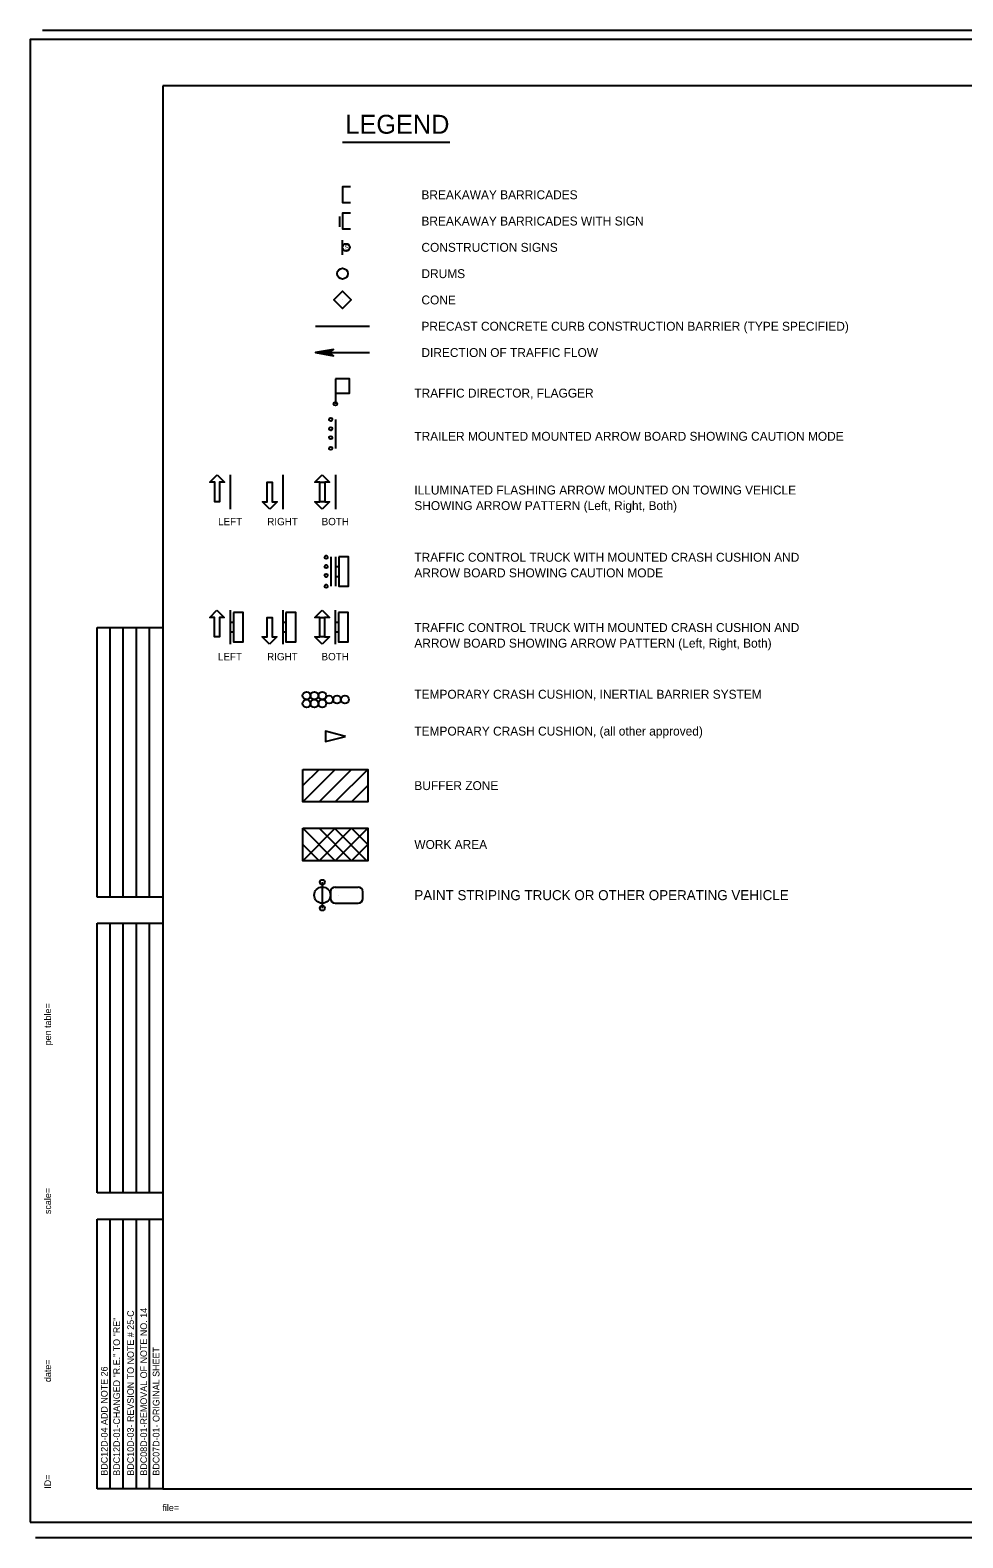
# Model space of a CAD drawing. Extents: x 499940 to 501011, y 499978 to 500655.
# Drawn here: x 499940 to 500359, y 499978 to 500655 of the extents above; entities that cross this region are included whole.
import ezdxf

# ---------------------------------------------------------------- set-up
doc = ezdxf.new("R2010")
doc.units = 0
for name, color, linetype in [('1', 7, 'Continuous'), ('24', 7, 'Continuous'), ('41', 7, 'Continuous'), ('5', 7, 'Continuous'), ('56', 7, 'Continuous'), ('60', 7, 'Continuous')]:
    doc.layers.add(name, color=color, linetype=linetype)

msp = doc.modelspace()

# ---------------------------------------------------------------- linework, layer by layer
at = {"layer": '1'}
for p, q in [((499946.02, 500655.04), (501011.03, 500655.04)), ((500000, 500630), (500000, 500000)), ((500990, 500630), (500000, 500630)), ((500080.76, 500604.79), (500128.92, 500604.79)), ((500080.76, 500533.87), (500080.76, 500533.87)), ((500068.59, 500522.06), (500092.93, 500522.06)), ((500068.59, 500510.25), (500092.93, 500510.25)), ((500077.56, 500480.24), (500077.56, 500467.1)), ((500030.32, 500455.29), (500030.32, 500439.95)), ((500053.94, 500455.29), (500053.94, 500439.95)), ((500077.56, 500455.29), (500077.56, 500442.14)), ((500077.56, 500455.29), (500077.56, 500439.95)), ((500075.51, 500418.52), (500075.51, 500405.38)), ((500077.56, 500418.52), (500077.56, 500405.38)), ((500077.56, 500414.14), (500079.02, 500414.14)), ((500077.56, 500409.76), (500079.02, 500409.76)), ((500030.26, 500394.63), (500030.26, 500379.29)), ((500053.88, 500394.63), (500053.88, 500379.29)), ((500077.5, 500394.63), (500077.5, 500379.29)), ((499970.47, 500265.75), (499970.47, 500386.81)), ((499970.47, 500386.81), (500000, 500386.81)), ((499976.38, 500265.75), (499976.38, 500386.81)), ((499982.28, 500265.75), (499982.28, 500386.81)), ((499988.19, 500265.75), (499988.19, 500386.81)), ((499994.09, 500265.75), (499994.09, 500386.81)), ((500030.26, 500389.15), (500031.72, 500389.15)), ((500053.88, 500389.15), (500055.34, 500389.15)), ((500077.5, 500389.15), (500078.96, 500389.15)), ((500030.26, 500384.77), (500031.72, 500384.77)), ((500053.88, 500384.77), (500055.34, 500384.77)), ((500077.5, 500384.77), (500078.96, 500384.77)), ((500071.66, 500272.44), (500071.66, 500260.76)), ((500000, 500265.75), (499970.47, 500265.75)), ((500075.31, 500268.06), (500075.31, 500265.14)), ((500077.5, 500270.25), (500087.72, 500270.25)), ((500078.96, 500266.6), (500078.96, 500266.6)), ((500089.91, 500265.14), (500089.91, 500268.06)), ((500077.5, 500262.95), (500087.72, 500262.95)), ((499970.47, 500132.87), (499970.47, 500253.94)), ((499970.47, 500253.94), (500000, 500253.94)), ((499976.38, 500132.87), (499976.38, 500253.94)), ((499982.28, 500132.87), (499982.28, 500253.94)), ((499988.19, 500132.87), (499988.19, 500253.94)), ((499994.09, 500132.87), (499994.09, 500253.94)), ((500000, 500132.87), (499970.47, 500132.87)), ((499970.47, 500000), (499970.47, 500121.06)), ((499970.47, 500121.06), (500000, 500121.06)), ((499976.38, 500000), (499976.38, 500121.06)), ((499982.28, 500000), (499982.28, 500121.06)), ((499988.19, 500000), (499988.19, 500121.06)), ((499994.09, 500000), (499994.09, 500121.06)), ((500000, 500000), (499970.47, 500000)), ((500000, 500000), (500990, 500000)), ((501007.77, 499977.98), (499942.76, 499977.98))]:
    msp.add_line(p, q, dxfattribs=at)
msp.add_lwpolyline([(500076.85, 500533.98), (500080.79, 500530.04), (500084.66, 500533.91), (500080.72, 500537.85)], close=True, dxfattribs=at)
msp.add_circle((500071.66, 500266.6), 3.65, dxfattribs=at)
for centre, start, end in [((500077.5, 500268.06), 90, 180), ((500077.5, 500265.14), 180, 270), ((500087.72, 500268.06), 0, 90), ((500087.72, 500265.14), 270, 0)]:
    msp.add_arc(centre, 2.19, start, end, dxfattribs=at)
at = {"layer": '24'}
msp.add_lwpolyline([(500068.59, 500510.25), (500076.68, 500508.82), (500074.75, 500510.25), (500076.64, 500511.66), (500068.59, 500510.25), (500069.12, 500510.27), (500076.46, 500508.93), (500074.6, 500510.27), (500076.31, 500511.55), (500069.41, 500510.29), (500069.68, 500510.25), (500075.96, 500509.14), (500074.56, 500510.27), (500076, 500511.37), (500069.81, 500510.25), (500070.08, 500510.29), (500075.57, 500509.3), (500074.5, 500510.25), (500075.59, 500511.24), (500070.86, 500510.29), (500071.31, 500510.29), (500075.16, 500509.51), (500074.41, 500510.23), (500075.22, 500511.04), (500071.4, 500510.25), (500071.83, 500510.23), (500074.72, 500509.73), (500074.16, 500510.29), (500074.77, 500510.85), (500072.23, 500510.25), (500072.63, 500510.21), (500074.37, 500509.88), (500074.08, 500510.27), (500074.56, 500510.7), (500072.85, 500510.25), (500073.98, 500509.98), (500073.81, 500510.29), (500074.31, 500510.6), (500073.13, 500510.29), (500073.87, 500510.11), (500073.56, 500510.35), (500073.92, 500510.5), (500073.56, 500510.27), (500073.75, 500510.23)], dxfattribs=at)
at = {"layer": '41'}
msp.add_lwpolyline([(499940.42, 499984.98), (501004.97, 499984.98), (501004.97, 500650.84), (499940.42, 500650.84)], close=True, dxfattribs=at)
at = {"layer": '5'}
msp.add_line((500077.56, 500492.05), (500077.56, 500487.26), dxfattribs=at)
msp.add_circle((500077.56, 500487.26), 0.799, dxfattribs=at)
at = {"layer": '56'}
for p, q in [((500079.35, 500571.43), (500079.35, 500566.78)), ((500080.76, 500554.21), (500080.76, 500560.78)), ((500062.9, 500308.48), (500077.5, 500323.08)), ((500062.9, 500315.78), (500070.2, 500323.08)), ((500070.2, 500308.48), (500084.8, 500323.08)), ((500077.5, 500308.48), (500092.11, 500323.08)), ((500084.8, 500308.48), (500092.11, 500315.78)), ((500062.9, 500282.06), (500077.5, 500296.66)), ((500077.5, 500282.06), (500062.9, 500296.66)), ((500070.2, 500282.06), (500084.8, 500296.66)), ((500084.8, 500282.06), (500070.2, 500296.66)), ((500091.72, 500282.06), (500077.12, 500296.66)), ((500077.5, 500282.06), (500092.11, 500296.66)), ((500092.11, 500289.36), (500084.8, 500296.66)), ((500070.2, 500282.06), (500062.9, 500289.36)), ((500084.8, 500282.06), (500092.11, 500289.36))]:
    msp.add_line(p, q, dxfattribs=at)
for points in [[(500084.26, 500584.62), (500080.76, 500584.62), (500080.76, 500581.12), (500080.76, 500577.61), (500084.26, 500577.61)], [(500084.26, 500572.81), (500080.76, 500572.81), (500080.76, 500569.31), (500080.76, 500565.8), (500084.26, 500565.8)], [(500024.41, 500455.29), (500027.7, 500452), (500025.51, 500452), (500025.51, 500443.24), (500023.32, 500443.24), (500023.32, 500452), (500021.13, 500452), (500024.41, 500455.29)], [(500071.66, 500455.29), (500074.94, 500452), (500072.75, 500452), (500072.75, 500443.24), (500070.56, 500443.24), (500070.56, 500452), (500068.37, 500452), (500071.66, 500455.29)], [(500048.03, 500439.95), (500044.75, 500443.24), (500046.94, 500443.24), (500046.94, 500452), (500049.13, 500452), (500049.13, 500443.24), (500051.32, 500443.24), (500048.03, 500439.95)], [(500071.66, 500439.95), (500068.37, 500443.24), (500070.56, 500443.24), (500070.56, 500452), (500072.75, 500452), (500072.75, 500443.24), (500074.94, 500443.24), (500071.66, 500439.95)], [(500024.35, 500394.62), (500027.64, 500391.34), (500025.45, 500391.34), (500025.45, 500382.57), (500023.26, 500382.57), (500023.26, 500391.34), (500021.07, 500391.34), (500024.35, 500394.62)], [(500071.6, 500394.62), (500074.88, 500391.34), (500072.69, 500391.34), (500072.69, 500382.57), (500070.5, 500382.57), (500070.5, 500391.34), (500068.31, 500391.34), (500071.6, 500394.62)], [(500047.98, 500379.29), (500044.69, 500382.57), (500046.88, 500382.57), (500046.88, 500391.34), (500049.07, 500391.34), (500049.07, 500382.57), (500051.26, 500382.57), (500047.98, 500379.29)], [(500071.6, 500379.29), (500068.31, 500382.57), (500070.5, 500382.57), (500070.5, 500391.34), (500072.69, 500391.34), (500072.69, 500382.57), (500074.88, 500382.57), (500071.6, 500379.29)], [(500082.03, 500337.87), (500073.04, 500340.26), (500073.04, 500335.53), (500082.03, 500337.87)], [(500062.9, 500323.08), (500092.11, 500323.08), (500092.11, 500308.48), (500062.9, 500308.48), (500062.9, 500323.08)], [(500062.9, 500296.66), (500092.11, 500296.66), (500092.11, 500282.06), (500062.9, 500282.06), (500062.9, 500296.66)]]:
    msp.add_lwpolyline(points, dxfattribs=at)
msp.add_lwpolyline([(500077.56, 500498.44), (500077.56, 500492.05), (500083.95, 500492.05), (500083.95, 500498.44)], close=True, dxfattribs=at)
for centre, radius in [((500082.4, 500557.5), 1.64), ((500080.76, 500545.69), 2.41), ((500064.58, 500356.18), 1.77), ((500064.58, 500352.63), 1.77), ((500068.12, 500356.18), 1.77), ((500068.12, 500352.63), 1.77), ((500071.66, 500356.18), 1.77), ((500071.66, 500352.63), 1.77), ((500074.73, 500354.41), 1.77), ((500078.27, 500354.41), 1.77), ((500081.81, 500354.41), 1.77)]:
    msp.add_circle(centre, radius, dxfattribs=at)
at = {"layer": '60'}
for points in [[(500080.72, 500537.85), (500076.85, 500533.98), (500080.79, 500530.04), (500084.66, 500533.91)], [(500077.56, 500498.44), (500077.56, 500492.05), (500083.95, 500492.05), (500083.95, 500498.44)], [(500024.41, 500455.29), (500027.7, 500452), (500025.51, 500452), (500025.51, 500443.24), (500023.32, 500443.24), (500023.32, 500452), (500021.13, 500452)], [(500071.66, 500455.29), (500074.94, 500452), (500072.75, 500452), (500072.75, 500443.24), (500070.56, 500443.24), (500070.56, 500452), (500068.37, 500452)], [(500048.03, 500439.95), (500044.75, 500443.24), (500046.94, 500443.24), (500046.94, 500452), (500049.13, 500452), (500049.13, 500443.24), (500051.32, 500443.24)], [(500071.66, 500439.95), (500068.37, 500443.24), (500070.56, 500443.24), (500070.56, 500452), (500072.75, 500452), (500072.75, 500443.24), (500074.94, 500443.24)], [(500079.02, 500418.52), (500079.02, 500405.38), (500083.4, 500405.38), (500083.4, 500418.52)], [(500024.35, 500394.62), (500027.64, 500391.34), (500025.45, 500391.34), (500025.45, 500382.57), (500023.26, 500382.57), (500023.26, 500391.34), (500021.07, 500391.34)], [(500031.72, 500393.53), (500031.72, 500380.39), (500036.1, 500380.39), (500036.1, 500393.53)], [(500055.34, 500393.53), (500055.34, 500380.39), (500059.72, 500380.39), (500059.72, 500393.53)], [(500071.6, 500394.62), (500074.88, 500391.34), (500072.69, 500391.34), (500072.69, 500382.57), (500070.5, 500382.57), (500070.5, 500391.34), (500068.31, 500391.34)], [(500078.96, 500393.53), (500078.96, 500380.39), (500083.34, 500380.39), (500083.34, 500393.53)], [(500047.98, 500379.29), (500044.69, 500382.57), (500046.88, 500382.57), (500046.88, 500391.34), (500049.07, 500391.34), (500049.07, 500382.57), (500051.26, 500382.57)], [(500071.6, 500379.29), (500068.31, 500382.57), (500070.5, 500382.57), (500070.5, 500391.34), (500072.69, 500391.34), (500072.69, 500382.57), (500074.88, 500382.57)], [(500082.03, 500337.87), (500073.04, 500340.26), (500073.04, 500335.53)]]:
    msp.add_lwpolyline(points, close=True, dxfattribs=at)
for centre, radius in [((500082.4, 500557.5), 1.64), ((500080.76, 500545.69), 2.41), ((500077.56, 500487.26), 0.799), ((500075.45, 500480.25), 0.73), ((500075.44, 500476.03), 0.73), ((500075.45, 500472.04), 0.73), ((500075.45, 500467.23), 0.73), ((500073.39, 500414.14), 0.73), ((500073.4, 500418.36), 0.73), ((500073.4, 500410.15), 0.73), ((500073.4, 500405.34), 0.73), ((500064.58, 500356.18), 1.77), ((500064.58, 500352.63), 1.77), ((500068.12, 500356.18), 1.77), ((500068.12, 500352.63), 1.77), ((500071.66, 500356.18), 1.77), ((500071.66, 500352.63), 1.77), ((500074.73, 500354.41), 1.77), ((500078.27, 500354.41), 1.77), ((500081.81, 500354.41), 1.77), ((500071.66, 500272.44), 1.1), ((500071.66, 500260.76), 1.1)]:
    msp.add_circle(centre, radius, dxfattribs=at)

# ---------------------------------------------------------------- texts
at = {"layer": '1'}
for s, height, p in [('...................pentable..................', 0.0432, (499949.83, 500223.07)), ('pen table=', 3, (499949.83, 500199.16)), ('......scale......', 0.0432, (499949.83, 500138.07)), ('scale=', 3, (499949.83, 500123.39)), ('BDC08D-01-REMOVAL OF NOTE NO. 14 ', 3, (499992.93, 500005.91)), ('BDC12D-01-CHANGED "R.E." TO "RE"', 3, (499980.77, 500005.86)), ('BDC10D-03- REVSION TO NOTE # 25-C', 3, (499987.03, 500005.91)), ('.......time......', 0.0432, (499949.83, 500061.07)), ('BDC07D-01- ORIGINAL SHEET', 3, (499998.52, 500005.91)), ('date=', 3, (499949.83, 500047.94)), ('BDC12D-04 ADD NOTE 26', 3, (499975.22, 500005.91)), ('............who............', 0.0432, (499949.83, 500008)), ('B', 3, (499992.93, 500005.91)), ('ID=', 3, (499949.83, 500000.03))]:
    msp.add_text(s, height=height, rotation=90, dxfattribs=at).set_placement(p)
for s, height, p in [('file=', 3, (499999.84, 499990)), ('...................bob..................', 0.0432, (500009.83, 499990))]:
    msp.add_text(s, height=height, dxfattribs=at).set_placement(p)
at = {"layer": '5'}
for s, height, p in [('LEGEND', 8.5, (500082.03, 500608.53)), ('BREAKAWAY BARRICADES', 4, (500116.19, 500579.12)), ('BREAKAWAY BARRICADES WITH SIGN', 4, (500116.19, 500567.31)), ('CONSTRUCTION SIGNS', 4, (500116.19, 500555.5)), ('DRUMS ', 4, (500116.19, 500543.69)), ('TRAFFIC DIRECTOR, FLAGGER', 4, (500113, 500490.05))]:
    msp.add_text(s, height=height, dxfattribs=at).set_placement(p)
at = {"layer": '56'}
for s, height, p in [('S', 2.19, (500081.73, 500556.4)), ('CONE', 4, (500116.19, 500531.87)), ('PRECAST CONCRETE CURB CONSTRUCTION BARRIER (TYPE SPECIFIED)', 4, (500116.19, 500520.06)), ('DIRECTION OF TRAFFIC FLOW', 4, (500116.19, 500508.25)), ('TRAILER MOUNTED MOUNTED ARROW BOARD SHOWING CAUTION MODE', 4, (500113, 500470.65)), ('ILLUMINATED FLASHING ARROW MOUNTED ON TOWING VEHICLE', 4, (500113, 500446.52)), ('SHOWING ARROW PATTERN (Left, Right, Both)', 4, (500113, 500439.52)), ('LEFT', 3.3, (500024.85, 500432.71)), ('RIGHT', 3.3, (500046.93, 500432.71)), ('BOTH', 3.3, (500071.37, 500432.71)), ('TRAFFIC CONTROL TRUCK WITH MOUNTED CRASH CUSHION AND', 4, (500113, 500416.32)), ('ARROW BOARD SHOWING CAUTION MODE', 4, (500113, 500409.32)), ('TRAFFIC CONTROL TRUCK WITH MOUNTED CRASH CUSHION AND', 4, (500113, 500384.76)), ('ARROW BOARD SHOWING ARROW PATTERN (Left, Right, Both)', 4, (500113, 500377.76)), ('LEFT', 3.3, (500024.8, 500372.05)), ('RIGHT', 3.3, (500046.87, 500372.05)), ('BOTH', 3.3, (500071.31, 500372.05)), ('TEMPORARY CRASH CUSHION, INERTIAL BARRIER SYSTEM', 4, (500113, 500354.8)), ('TEMPORARY CRASH CUSHION, (all other approved) ', 4, (500113, 500338.26)), ('BUFFER ZONE', 4, (500113, 500313.78)), ('WORK AREA', 4, (500113, 500287.36)), ('PAINT STRIPING TRUCK OR OTHER OPERATING VEHICLE', 4.5, (500113, 500264.35))]:
    msp.add_text(s, height=height, dxfattribs=at).set_placement(p)

doc.saveas('drawing.dxf')
